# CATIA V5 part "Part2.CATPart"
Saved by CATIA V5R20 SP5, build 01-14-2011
Part number: base
Publications: "Point.1", "Point.2", "Point.3", "Droite.1", "Droite.2", "Point.4", "Point.5", "Droite.3", "Droite.4", "Droite.5", "Angle_glissiere", "L3"
Bounding box of the stored display mesh (mm): x 0 to 0, y 0 to 153.743, z 0 to 69.9
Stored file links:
  F:\fpittorino_IAO\IAO_fpittorino_CATIA\Part2.CATPart
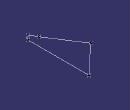
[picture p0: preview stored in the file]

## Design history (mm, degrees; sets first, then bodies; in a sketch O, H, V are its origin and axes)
Parameters
  l1 = 30 mm
  L2 = 135 mm
  L3 = 70 mm
  AREA = 0.044925 (area) {= (l1 +L2 )**2+22600 mm2 -L3 **2}
  LENGTH = 49.6099 mm {= 2*(l1 +L2 )*sqrt(22600 mm2)}
  Angle_glissiere = 45 deg
Body1 (main body)
  Point1: (0, 0, 0)
  Point2: (0, 0, 10)
  Point3: (0, 150, 0), relative to Point1
  Line1: type PtPt, FirstPoint Point3, SecondPoint Point1
  Line2: type PtPt, FirstPoint Point1, SecondPoint Point2
  Point4: (0, 27.9533 {= l1 *cos( acos( AREA /LENGTH )-3.814 deg)}, 10.8909 {= l1 *sin( acos( AREA /LENGTH )-3.814 deg)}), relative to Point2
  Point5: (0, 125.7899 {= L2 *cos( acos( AREA /LENGTH )-3.814 deg)}, 49.0091 {= L2 *sin( acos( AREA /LENGTH )-3.814 deg)}), relative to Point4
  Line3: type PtPt, FirstPoint Point2, SecondPoint Point4
  Line4: type PtPt, FirstPoint Point5, SecondPoint Point3
  Line5: type PtPt, FirstPoint Point4, SecondPoint Point5
Relations
  Point5.Z = *sin(acos(((l1 +L2 )*(l1 +L2 )+22600mm-(L3 *L3 ))/(2*(l1 +L2 )*sqrt(22600))-atan(1/15))) (deactivated)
